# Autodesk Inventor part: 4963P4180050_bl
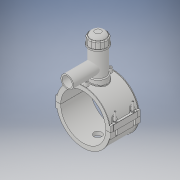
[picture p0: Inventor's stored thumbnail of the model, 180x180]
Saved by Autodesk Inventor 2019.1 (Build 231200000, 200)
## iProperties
Created: 2017-07
Part Number: 4963P4180050_bl
Material: Generic
Document SubType Name: Modeling
Designer: KIM
Density: 1 g/cm^3
Appearance: Default
Author: KIM
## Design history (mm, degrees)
derived "4963P4.ipt"
feature "Solid1::4963P4.ipt" dims "ScaleForDerivedMember" = 10
feature "Solid2::4963P4.ipt" dims "ScaleForDerivedMember" = 10
feature "Solid3::4963P4.ipt" dims "ScaleForDerivedMember" = 10
tag "TaggingFeature1"
body "Solid1"
body "Solid2"
body "Solid3"
other parameters: "d2" = 219 [user parameter], "d3" = 45 [user parameter], "d4" = 118 [user parameter], "d5" = 0 [user parameter], "d6" = 0.1 [user parameter], "d8" = 0 [user parameter], "d19" = 6 [user parameter], "d20" = 6 [user parameter], "d21" = 70.8 [user parameter], "d23" = 0 [user parameter], "d24" = 35.4 [user parameter], "d26" = 0 [user parameter], "d27" = 3 [user parameter], "d28" = 3 [user parameter], "d29" = 3 [user parameter], "d31" = 6 [user parameter], "d32" = 0 [user parameter], "d33" = 0 [user parameter], "d34" = 0.6 [user parameter], "d40" = 108.576 [user parameter], "d41" = 72 [user parameter], "d43" = 0 [user parameter], "d45" = 0 [user parameter], "d47" = 175.2 [user parameter], "d70" = 15 [user parameter], "d72" = 0 [user parameter], "d73" = 6 [user parameter], "d75" = 5 [user parameter], "d76" = 0 [user parameter], "d77" = 9 [user parameter], "d79" = 15 [user parameter], "d80" = 47.2 [user parameter], "d82" = 5 deg [user parameter], "d84" = 4 [user parameter], "d85" = 14 [user parameter], "d86" = 0 [user parameter], "d87" = 3 [user parameter], "d88" = 0 [user parameter], "d89" = 1 [user parameter], "d90" = 1 [user parameter], "d91" = 94.4 [user parameter], "d92" = 0 [user parameter], "d93" = 0.5 [user parameter], "d94" = 94.73684 [user parameter], "d96" = 212.976 [user parameter], "d97" = 2.36 [user parameter], "d98" = 0 [user parameter], "d102" = 1.8 [user parameter], "d120" = 140 deg [user parameter], "d121" = 24.228 [user parameter], "d122" = 20 deg [user parameter], "d123" = 417.6 [user parameter], "d124" = 125.28 [user parameter], "d126" = 0 [user parameter], "d143" = 185.4 [user parameter], "d145" = 22.15385 [user parameter], "d149" = 2.7 [user parameter], "d150" = 24.36923 [user parameter], "d153" = 118 [user parameter], "d154" = 0 [user parameter], "d156" = 104.4 [user parameter], "d157" = 160 deg [user parameter], "d159" = 5.76 [user parameter], "d161" = 2.7 [user parameter], "d162" = 70.8 [user parameter], "d163" = 0 [user parameter], "d167" = 18 [user parameter], "d168" = 101.85366 [user parameter], "d170" = 3.75 [user parameter], "d172" = 0 [user parameter], "d173" = 1 [user parameter], "d176" = 20 deg [user parameter], "d177" = 12.6 [user parameter], "d178" = 28.8 [user parameter], "d180" = 0 [user parameter], "d183" = 11.52 [user parameter], "d184" = 10.08 [user parameter], "d185" = 38.35 [user parameter], "d186" = 38.35 [user parameter], "d187" = 104.4 [user parameter], "d188" = 8.64 [user parameter], "d189" = 12.6 [user parameter], "d190" = 0 [user parameter], "d191" = 156.6 [user parameter], "d193" = 8 [user parameter], "d194" = 4.13 [user parameter], "d195" = 90 deg [user parameter], "d197" = 0 [user parameter], "d199" = 0 [user parameter], "d200" = 14.4 [user parameter], "d202" = 0 [user parameter], "d203" = 177 [user parameter], "d204" = 68.4 [user parameter], "d205" = 50.4 [user parameter], "d206" = 61.2 [user parameter], "d207" = 132.75 [user parameter], "d208" = 138.06 [user parameter], "d209" = 164.61 [user parameter], "d210" = 61.92 [user parameter], "d211" = 72 [user parameter], "d212" = 57.6 [user parameter], "d213" = 35.1 [user parameter], "d216" = 0 [user parameter], "d217" = 18 [user parameter], "d218" = 18 [user parameter], "d219" = 3.6 [user parameter], "d224" = 0 [user parameter], "d225" = 64 [user parameter], "d228" = 123 [user parameter], "d230" = 3.6 [user parameter], "B_" = 219 [user parameter], "L_" = 118 [user parameter], "d_t" = 6 [user parameter], "H_2" = 177 [user parameter], "H_1" = 64 [user parameter], "H_" = 123 [user parameter], "d1" = 208.8 [user parameter], "d148" = 2.7 [user parameter], "d160" = 2.7 [user parameter], "d169" = 3.75 [user parameter]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
